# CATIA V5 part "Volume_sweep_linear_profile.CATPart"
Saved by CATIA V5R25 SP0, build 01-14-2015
Part number: Part1
Bounding box of the stored display mesh (mm): x -63.725 to 63.725, y -58.359 to 47.359, z -20 to 20
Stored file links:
  E:\cadcim\GSD_cat_v5-6r2014\Part_files\Volume_sweep_linear_profile.CATPart
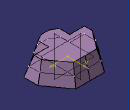
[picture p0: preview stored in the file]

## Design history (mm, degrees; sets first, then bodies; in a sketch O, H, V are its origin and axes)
Set1
  Sketch1 on xy-plane, origin (0, 0, 0), H (1, 0, 0), V (0, 1, 0)
    point P1 (0, 42)
    line L1 (0, 42) -> (-27.5, 42)
    point P2 (-27.5, 42)
    line L2 (-27.5, 42) -> (-58.3665, 0)
    point P3 (-58.3665, 0)
    line L3 (-58.3665, 0) -> (-58.3665, -23)
    point P4 (-58.3665, -23)
    line L4 (-58.3665, -23) -> (-27.5, -23)
    point P5 (-27.5, -23)
    line L5 (-27.5, -23) -> (-27.5, -42.8964)
    point P6 (-27.5, -42.8964)
    line L6 (-27.5, -42.8964) -> (-10, -53)
    point P7 (-10, -53)
    line L7 (-10, -53) -> (0, -53)
    point P8 (0, -53)
    reference intersected line E1 through (0, 0) direction (0, 1) from yz-plane
    point P11 (0, 0)
    construction line L8 through (0, 0) direction (0, 1)
    point P12 (0, 42)
    point P13 (27.5, 42)
    point P14 (58.3665, 0)
    point P15 (58.3665, -23)
    point P16 (27.5, -23)
    point P17 (27.5, -42.8964)
    point P18 (10, -53)
    point P19 (0, -53)
    line L9 (0, 42) -> (27.5, 42)
    line L10 (27.5, 42) -> (58.3665, 0)
    line L11 (58.3665, 0) -> (58.3665, -23)
    line L12 (58.3665, -23) -> (27.5, -23)
    line L13 (27.5, -23) -> (27.5, -42.8964)
    line L14 (27.5, -42.8964) -> (10, -53)
    line L15 (10, -53) -> (0, -53)
    distance P14 P13 V = 42
    distance P13 P2 = 55
    distance P15 P14 = 23
    distance L11 L8 = 58.3665
    angle L14 L15 = 30
    distance P18 P7 = 20
    distance P17 P6 = 55
    distance L9 L15 = 95
    coincidence: P1 V, P3 H, P8 V, P7 L15, P8 L15, P18 L7, P19 L7
    horizontal: L1 H, L4 H, L7 H, L15 H
    vertical: L3 V, L5 V
    symmetry: O P11 E1, V L8 E1, P1 P12 E1, P2 P13 E1, P3 P14 E1, P4 P15 E1, P5 P16 E1, P6 P17 E1, P7 P18 E1, P8 P19 E1, L1 L9 E1, L2 L10 E1, L3 L11 E1, L4 L12 E1, L5 L13 E1, L6 L14 E1, L7 L15 E1
  Sweep1: type Segment, GuideCrv Sketch1, Length1 20, Length2 20, Angle 15, DraftDirection xy-plane
Body1 (main body)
